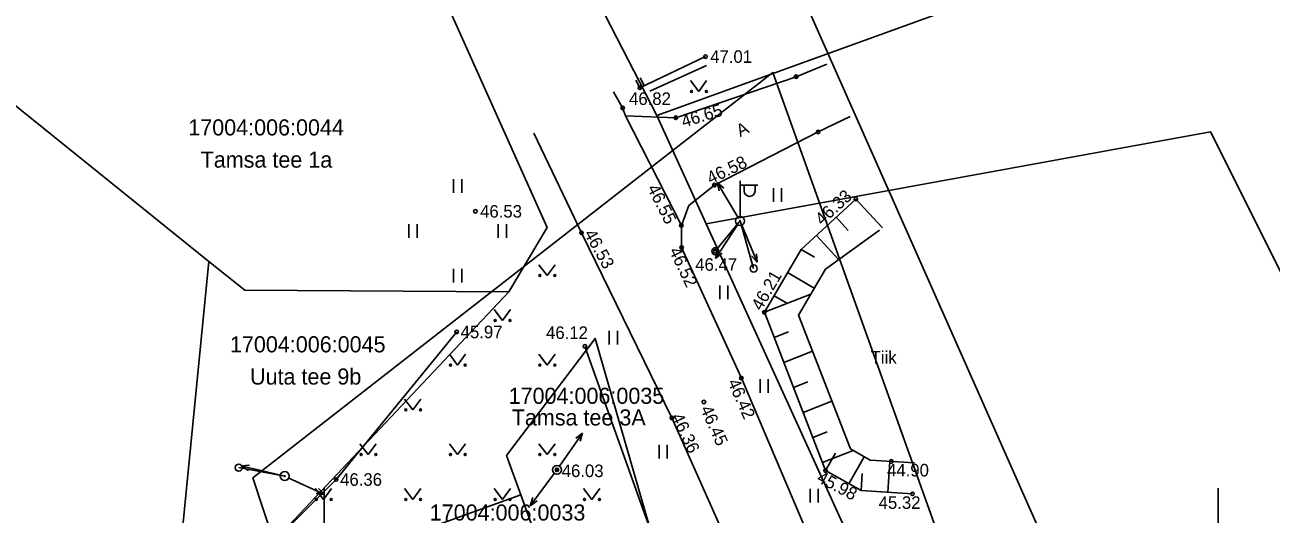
# Model space of a CAD drawing. Extents: x 642747 to 644424, y 6457048 to 6458238.
# Drawn here: x 644033.3 to 644103, y 6457750.5 to 6457777.9 of the extents above; entities that cross this region are included whole.
import ezdxf

# ---------------------------------------------------------------- set-up
doc = ezdxf.new("R2010")
doc.units = 0
for name, color, linetype in [('AED', 7, 'Continuous'), ('HALJASTUS', 7, 'Continuous'), ('KORGUS', 7, 'Continuous'), ('MOOTPIIR', 7, 'Continuous'), ('MPOHULIIN', 7, 'Continuous'), ('PIIR', 7, 'Continuous'), ('POST', 7, 'Continuous'), ('RELJEEF', 7, 'Continuous'), ('TEE', 7, 'Continuous'), ('VEEKOGU', 7, 'Continuous'), ('VORK', 7, 'Continuous'), ('VORMISTUS', 7, 'Continuous')]:
    doc.layers.add(name, color=color, linetype=linetype)

msp = doc.modelspace()

# ---------------------------------------------------------------- linework, layer by layer
at = {"layer": 'AED'}
for points in [[(644067.438, 6457774.791), (644067.658, 6457774.369), (644071.331, 6457776.106)], [(644050.678, 6457752.48), (644057.417, 6457760.724)], [(644064.587, 6457759.915), (644069.655, 6457745.733), (644073.82, 6457731.123)], [(644050.678, 6457752.48), (644041.468, 6457743.292)]]:
    msp.add_lwpolyline(points, dxfattribs=at)
at = {"layer": 'HALJASTUS'}
for p, q in [((644068.224, 6457774.167), (644071.39, 6457775.606)), ((644067.679, 6457774.916), (644067.896, 6457774.496)), ((644070.485, 6457774.768), (644070.949, 6457774.161)), ((644070.949, 6457774.161), (644071.394, 6457774.768)), ((644057.244, 6457769.249), (644057.244, 6457768.488)), ((644057.699, 6457769.249), (644057.699, 6457768.488)), ((644075.127, 6457768.752), (644075.127, 6457767.991)), ((644075.582, 6457768.752), (644075.582, 6457767.991)), ((644054.744, 6457766.749), (644054.744, 6457765.988)), ((644055.199, 6457766.749), (644055.199, 6457765.988)), ((644059.744, 6457766.749), (644059.744, 6457765.988)), ((644060.199, 6457766.749), (644060.199, 6457765.988)), ((644062.008, 6457764.475), (644062.471, 6457763.869)), ((644062.471, 6457763.869), (644062.917, 6457764.475)), ((644057.244, 6457764.249), (644057.244, 6457763.488)), ((644057.699, 6457764.249), (644057.699, 6457763.488)), ((644072.126, 6457763.311), (644072.126, 6457762.55)), ((644072.581, 6457763.311), (644072.581, 6457762.55)), ((644059.508, 6457761.975), (644059.971, 6457761.369)), ((644059.971, 6457761.369), (644060.417, 6457761.975)), ((644065.945, 6457760.782), (644065.945, 6457760.021)), ((644066.401, 6457760.782), (644066.401, 6457760.021)), ((644057.008, 6457759.475), (644057.471, 6457758.869)), ((644057.471, 6457758.869), (644057.917, 6457759.475)), ((644062.008, 6457759.475), (644062.471, 6457758.869)), ((644062.471, 6457758.869), (644062.917, 6457759.475)), ((644074.384, 6457758.079), (644074.384, 6457757.317)), ((644074.839, 6457758.079), (644074.839, 6457757.317)), ((644054.508, 6457756.975), (644054.971, 6457756.369)), ((644054.971, 6457756.369), (644055.417, 6457756.975)), ((644052.008, 6457754.475), (644052.471, 6457753.869)), ((644052.471, 6457753.869), (644052.917, 6457754.475)), ((644057.008, 6457754.475), (644057.471, 6457753.869)), ((644057.471, 6457753.869), (644057.917, 6457754.475)), ((644062.008, 6457754.475), (644062.471, 6457753.869)), ((644062.471, 6457753.869), (644062.917, 6457754.475)), ((644068.739, 6457754.419), (644068.739, 6457753.658)), ((644069.194, 6457754.419), (644069.194, 6457753.658)), ((644049.508, 6457751.975), (644049.971, 6457751.369)), ((644049.971, 6457751.369), (644050.417, 6457751.975)), ((644054.508, 6457751.975), (644054.971, 6457751.369)), ((644054.971, 6457751.369), (644055.417, 6457751.975)), ((644059.508, 6457751.975), (644059.971, 6457751.369)), ((644059.971, 6457751.369), (644060.417, 6457751.975)), ((644064.508, 6457751.975), (644064.971, 6457751.369)), ((644064.971, 6457751.369), (644065.417, 6457751.975)), ((644077.177, 6457751.954), (644077.177, 6457751.193)), ((644077.632, 6457751.954), (644077.632, 6457751.193))]:
    msp.add_line(p, q, dxfattribs=at)
for centre in [(644070.548, 6457774.161), (644071.377, 6457774.161), (644062.07, 6457763.869), (644062.899, 6457763.869), (644059.57, 6457761.369), (644060.399, 6457761.369), (644057.07, 6457758.869), (644057.899, 6457758.869), (644062.07, 6457758.869), (644062.899, 6457758.869), (644054.57, 6457756.369), (644055.399, 6457756.369), (644052.07, 6457753.869), (644052.899, 6457753.869), (644057.07, 6457753.869), (644057.899, 6457753.869), (644062.07, 6457753.869), (644062.899, 6457753.869), (644049.57, 6457751.369), (644050.399, 6457751.369), (644054.57, 6457751.369), (644055.399, 6457751.369), (644059.57, 6457751.369), (644060.399, 6457751.369), (644064.57, 6457751.369), (644065.399, 6457751.369)]:
    msp.add_circle(centre, 0.055, dxfattribs=at)
at = {"layer": 'KORGUS'}
for centre in [(644071.331, 6457776.106), (644076.396, 6457774.983), (644067.658, 6457774.369), (644066.696, 6457773.238), (644069.668, 6457772.69), (644077.628, 6457771.896), (644071.826, 6457768.928), (644079.735, 6457768.149), (644058.465, 6457767.461), (644069.979, 6457766.674), (644064.397, 6457766.262), (644069.994, 6457765.435), (644071.878, 6457765.231), (644074.619, 6457761.82), (644057.417, 6457760.724), (644064.587, 6457759.915), (644073.333, 6457758.14), (644071.239, 6457756.81), (644069.452, 6457755.916), (644081.723, 6457753.488), (644050.678, 6457752.48), (644063.025, 6457753.02), (644078.041, 6457752.979), (644082.901, 6457751.677)]:
    msp.add_circle(centre, 0.1, dxfattribs=at)
at = {"layer": 'MOOTPIIR'}
msp.add_lwpolyline([(643525.446, 6457467.559), (643537.447, 6457435.458), (643944.848, 6457628.51), (644046.626, 6457529.09), (644067.022, 6457529.09), (644138.408, 6457598.401), (644075.1, 6457775.215), (644046.02, 6457752.582), (644092.466, 6457611.94), (644070.657, 6457576.375), (644041.981, 6457570.717), (643942.223, 6457662.862)], close=True, dxfattribs=at)
at = {"layer": 'MPOHULIIN'}
for p, q in [((644071.989, 6457769.077), (644072.089, 6457768.612)), ((644071.989, 6457769.077), (644072.346, 6457768.763)), ((644073.133, 6457767.139), (644071.989, 6457769.077)), ((644073.123, 6457766.715), (644071.892, 6457764.831)), ((644073.355, 6457766.693), (644074.213, 6457764.613)), ((644071.892, 6457764.831), (644072.015, 6457765.291)), ((644071.892, 6457764.831), (644072.264, 6457765.127)), ((644074.213, 6457764.613), (644074.18, 6457765.087)), ((644074.213, 6457764.613), (644073.903, 6457764.974)), ((644063.168, 6457753.225), (644064.458, 6457755.068)), ((644064.458, 6457755.068), (644064.076, 6457754.785)), ((644064.458, 6457755.068), (644064.32, 6457754.613)), ((644045.368, 6457753.235), (644045.841, 6457753.277)), ((644045.368, 6457753.235), (644045.773, 6457752.987)), ((644047.559, 6457752.726), (644045.368, 6457753.235)), ((644047.986, 6457752.579), (644050.033, 6457751.646)), ((644062.875, 6457752.819), (644061.53, 6457751.016)), ((644050.033, 6457751.646), (644049.685, 6457751.97)), ((644050.033, 6457751.646), (644049.561, 6457751.698)), ((644061.53, 6457751.016), (644061.681, 6457751.467)), ((644061.53, 6457751.016), (644061.92, 6457751.288))]:
    msp.add_line(p, q, dxfattribs=at)
at = {"layer": 'PIIR'}
for points in [[(644068.6, 6457772.82), (644090.15, 6457780.61), (644096.69, 6457813.79), (644090.79, 6457817.22), (644082.89, 6457819.08), (644073.49, 6457814.92), (644052.27, 6457804.54)], [(644068.6, 6457772.82), (644071.37, 6457766.77), (644099.56, 6457771.91), (644110.27, 6457750.55), (644133.56, 6457751.83), (644130.81, 6457757.16), (644122.42, 6457773.43), (644108.05, 6457801.29), (644096.69, 6457813.79), (644090.15, 6457780.61)], [(643987.33, 6457763.78), (643989.66, 6457760.08), (644041.41, 6457742.89), (644043.56, 6457764.65), (644025.09, 6457779.53), (644002.87, 6457796.77), (643999.66, 6457800.61)], [(644056.78, 6457779.28), (644025.09, 6457779.53), (644043.56, 6457764.65), (644045.58, 6457763.06), (644060.34, 6457762.97), (644062.47, 6457766.56)], [(644060.34, 6457762.97), (644045.58, 6457763.06), (644043.56, 6457764.65), (644041.41, 6457742.89)], [(644065.16, 6457760.36), (644060.21, 6457753.82), (644061, 6457751.62), (644064.35, 6457742.34), (644069.76, 6457744.43)], [(644064.35, 6457742.34), (644061, 6457751.62), (644055.31, 6457749.58), (644058.72, 6457740.17)]]:
    msp.add_lwpolyline(points, close=True, dxfattribs=at)
for points in [[(644172.44, 6457634.51), (644128.57, 6457664.58), (644105.62, 6457695.4), (644084.27, 6457738.29), (644082.35, 6457742.69), (644071.37, 6457766.77), (644068.6, 6457772.82), (644052.27, 6457804.54)], [(644056.78, 6457779.28), (644062.47, 6457766.56), (644060.34, 6457762.97), (644041.41, 6457742.89), (644054.5, 6457738.54), (644058.72, 6457740.17), (644055.31, 6457749.58), (644061, 6457751.62), (644060.21, 6457753.82), (644065.16, 6457760.36), (644069.76, 6457744.43), (644073.59, 6457731.16), (644087.56, 6457695.23), (644092.09, 6457697.08), (644102.74, 6457676.12), (644108.68, 6457668.18), (644119.21, 6457655.5), (644137.18, 6457639.57)]]:
    msp.add_lwpolyline(points, dxfattribs=at)
at = {"layer": 'POST'}
for p, q in [((644073.26, 6457767.174), (644073.26, 6457769.174)), ((644073.26, 6457768.924), (644074.26, 6457768.924)), ((644073.487, 6457768.603), (644073.487, 6457768.924)), ((644074.099, 6457768.603), (644074.099, 6457768.924)), ((644071.878, 6457765.231), (644073.26, 6457766.924)), ((644073.26, 6457766.924), (644074.022, 6457764.269)), ((644073.26, 6457766.924), (644073.26, 6457766.924))]:
    msp.add_line(p, q, dxfattribs=at)
msp.add_lwpolyline([(644045.231, 6457753.142), (644047.803, 6457752.67)], dxfattribs=at)
for centre, radius in [((644073.26, 6457766.924), 0.25), ((644073.26, 6457766.924), 0.0234), ((644071.878, 6457765.231), 0.2), ((644074.022, 6457764.269), 0.2), ((644045.231, 6457753.142), 0.2), ((644063.025, 6457753.02), 0.25), ((644047.803, 6457752.67), 0.25), ((644047.803, 6457752.67), 0.0234), ((644063.025, 6457753.02), 0.0234)]:
    msp.add_circle(centre, radius, dxfattribs=at)
msp.add_arc((644073.793, 6457768.603), 0.306, 180, 0, dxfattribs=at)
at = {"layer": 'RELJEEF'}
for p, q in [((644079.735, 6457768.149), (644081.222, 6457766.536)), ((644078.632, 6457767.132), (644079.315, 6457766.391)), ((644077.529, 6457766.116), (644078.774, 6457764.765)), ((644076.679, 6457765.332), (644077.425, 6457764.894)), ((644075.92, 6457764.038), (644077.413, 6457763.162)), ((644074.619, 6457761.82), (644077.215, 6457762.825)), ((644075.161, 6457762.744), (644075.907, 6457762.306)), ((644075.16, 6457760.421), (644075.967, 6457760.733)), ((644075.702, 6457759.022), (644077.316, 6457759.647)), ((644076.243, 6457757.623), (644077.05, 6457757.936)), ((644076.785, 6457756.224), (644078.399, 6457756.849)), ((644077.326, 6457754.826), (644078.133, 6457755.138)), ((644077.868, 6457753.427), (644079.591, 6457754.094)), ((644078.041, 6457752.979), (644078.59, 6457753.958)), ((644079.349, 6457752.245), (644080.196, 6457753.754)), ((644081.526, 6457751.766), (644081.638, 6457753.493)), ((644080.029, 6457751.863), (644080.091, 6457752.821))]:
    msp.add_line(p, q, dxfattribs=at)
msp.add_lwpolyline([(644079.735, 6457768.149), (644076.679, 6457765.332), (644074.619, 6457761.82), (644078.041, 6457752.979), (644080.029, 6457751.863), (644082.901, 6457751.677)], dxfattribs=at)
at = {"layer": 'TEE'}
for points in [[(644079.412, 6457772.758), (644077.628, 6457771.896), (644071.826, 6457768.928), (644070.393, 6457767.784), (644069.979, 6457766.674), (644066.852, 6457772.801), (644069.668, 6457772.69), (644076.396, 6457774.983), (644078.116, 6457775.691)], [(644066.852, 6457772.801), (644066.696, 6457773.238), (644066.185, 6457774.14)], [(644061.722, 6457771.823), (644064.397, 6457766.262), (644069.452, 6457755.916), (644076.842, 6457739.337), (644084.183, 6457724.283), (644091.562, 6457708.571), (644100.441, 6457690.483), (644108.831, 6457675.729), (644120.122, 6457661.417), (644128.409, 6457653.611)], [(644104.514, 6457693.442), (644104.136, 6457693.495), (644095.975, 6457711.092), (644088.251, 6457726.755), (644080.737, 6457740.751), (644073.333, 6457758.14), (644069.994, 6457765.435), (644069.979, 6457766.674)]]:
    msp.add_lwpolyline(points, dxfattribs=at)
at = {"layer": 'VEEKOGU'}
msp.add_lwpolyline([(644081.049, 6457766.411), (644078.041, 6457764.234), (644076.534, 6457761.665), (644079.431, 6457754.184), (644080.534, 6457753.565), (644083.014, 6457753.404)], dxfattribs=at)
at = {"layer": 'VORK'}
for p, q in [((644050, 6457752), (644050, 6457748)), ((644100, 6457752), (644100, 6457748))]:
    msp.add_line(p, q, dxfattribs=at)
at = {"layer": 'VORMISTUS'}
msp.add_line((644034.968, 6457873.554), (644180.435, 6457546.05), dxfattribs=at)

# ---------------------------------------------------------------- texts
at = {"layer": 'KORGUS'}
for s, p in [(' 47.01', (644071.331, 6457775.756)), (' 46.82', (644066.794, 6457773.404)), (' 46.53', (644058.465, 6457767.111)), (' 46.47', (644070.496, 6457764.142)), ('45.97', (644057.638, 6457760.374)), (' 46.12', (644062.152, 6457760.335)), ('46.03', (644063.289, 6457752.614)), (' 44.90', (644081.22, 6457752.651)), ('46.36', (644050.899, 6457752.13)), (' 45.32', (644080.749, 6457750.84))]:
    msp.add_text(s, height=0.7, dxfattribs=at).set_placement(p)
for s, rotation, p in [(' 46.65', 16.92942, (644069.853, 6457772.06)), (' 46.58', 25.58396, (644071.376, 6457768.846)), (' 46.55', 296.91421, (644067.936, 6457768.992)), (' 46.33', 42.23743, (644077.652, 6457766.466)), (' 46.53', 299.09972, (644064.393, 6457766.446)), (' 46.52', 295.39672, (644069.163, 6457765.5)), (' 46.21', 59.94588, (644074.321, 6457761.639)), (' 46.42', 293.9115, (644072.444, 6457758.159)), (' 46.36', 295.437, (644069.288, 6457756.222)), (' 46.45', 294.02197, (644070.919, 6457756.668)), (' 45.98', 332.27545, (644077.269, 6457752.498))]:
    msp.add_text(s, height=0.7, rotation=rotation, dxfattribs=at).set_placement(p)
at = {"layer": 'PIIR'}
for s, p in [('17004:006:0044', (644042.41, 6457771.7)), ('Tamsa tee 1a', (644043.1, 6457769.9)), ('17004:006:0045', (644044.739, 6457759.582)), ('Uuta tee 9b', (644045.863, 6457757.782)), ('17004:006:0035', (644060.323, 6457756.707)), ('Tamsa tee 3A', (644060.495, 6457755.497)), ('17004:006:0033', (644055.91, 6457750.186))]:
    msp.add_text(s, height=0.9, dxfattribs=at).set_placement(p)
at = {"layer": 'TEE'}
msp.add_text('A', height=0.7, rotation=27.08859, dxfattribs=at).set_placement((644073.269, 6457771.598))
at = {"layer": 'VEEKOGU'}
msp.add_text('Tiik', height=0.7, dxfattribs=at).set_placement((644080.563, 6457758.953))

doc.saveas('drawing.dxf')
